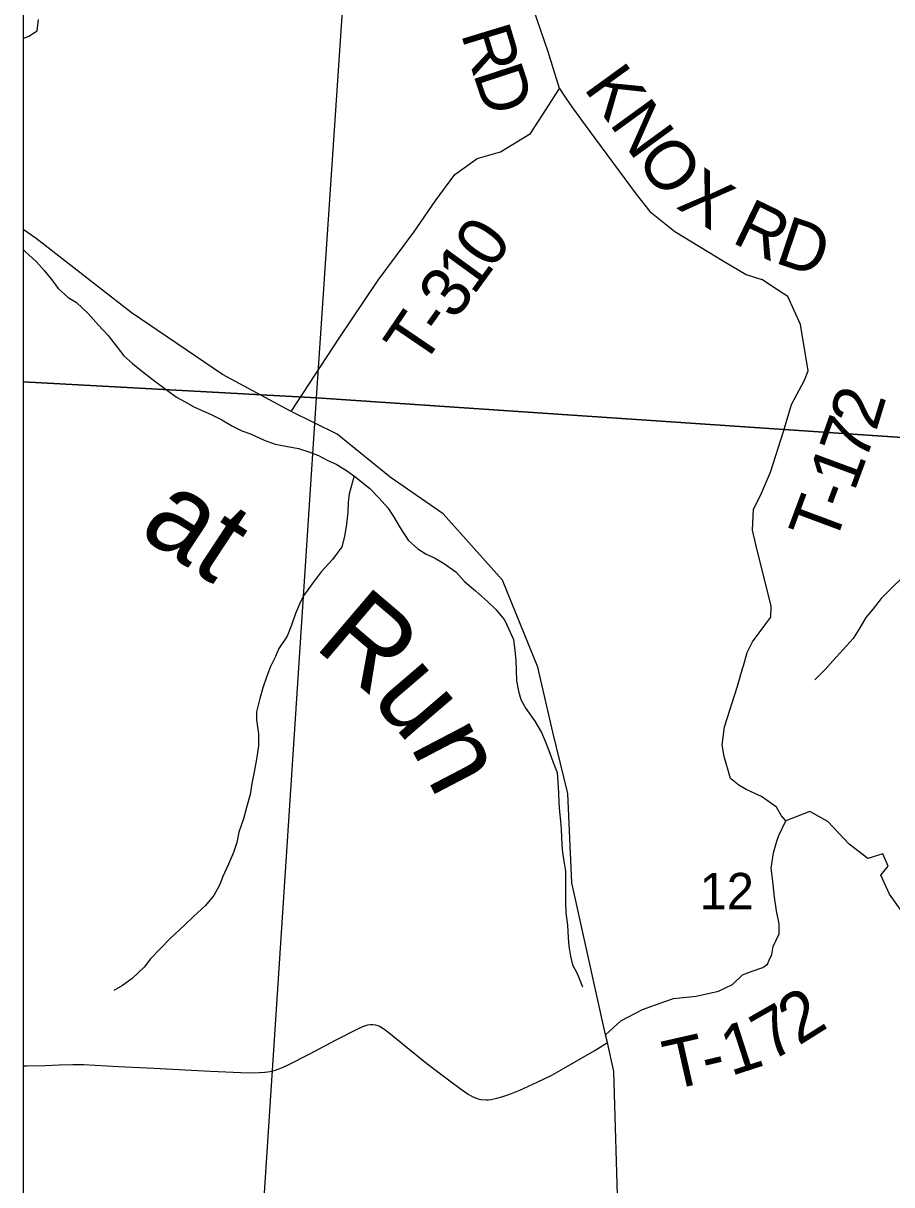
# Model space of a CAD drawing. Extents: x 0 to 34, y 0 to 22.
# Drawn here: x 2.1 to 3.095, y 17.112 to 18.443 of the extents above; entities that cross this region are included whole.
import ezdxf

# ---------------------------------------------------------------- set-up
doc = ezdxf.new("R2010")
doc.units = 0
for name, color, linetype in [('GM_X_Corporation', 7, 'Continuous'), ('GM_X_County_Road', 7, 'Continuous'), ('GM_X_Minor_River', 7, 'Continuous'), ('GM_X_Minor_River_Text', 7, 'Continuous'), ('GM_X_Section_Text', 7, 'Continuous'), ('GM_X_Township_Road', 7, 'Continuous'), ('GM_X_Township_Road_Text', 7, 'Continuous'), ('SH_Data', 7, 'Continuous')]:
    doc.layers.add(name, color=color, linetype=linetype)

msp = doc.modelspace()

# ---------------------------------------------------------------- linework, layer by layer
at = {"layer": 'GM_X_Corporation'}
for points in [[(2.1, 19.0816), (2.1, 14.1), (3.1902, 14.1), (3.1919, 14.1255), (3.2339, 14.7735), (3.2844, 15.554), (3.3059, 15.8844), (3.3516, 16.5898), (3.3951, 17.2616), (3.507, 18.9883), (2.9513, 19.0267), (2.509, 19.0572), (2.4972, 19.0545), (2.4649, 19.0567)], [(2.1, 19.0812), (2.1, 18.0323), (2.436, 18.0137), (2.5061, 19.0541)], [(2.5061, 19.0541), (2.5182, 19.0533), (3.5166, 18.9866), (3.4457, 17.9455), (2.436, 18.0137)], [(2.1, 18.0323), (2.1, 16.9887), (2.3682, 16.9741), (2.436, 18.0137)], [(2.436, 18.0137), (3.4457, 17.9455), (3.3779, 16.9127), (2.3682, 16.9741)]]:
    msp.add_lwpolyline(points, close=True, dxfattribs=at)
at = {"layer": 'GM_X_County_Road'}
for points in [[(2.7818, 17.0745), (2.777, 17.2417), (2.7694, 17.2751), (2.7674, 17.2839), (2.7452, 17.3837), (2.7286, 17.4581), (2.7242, 17.5602), (2.7069, 17.6307), (2.6896, 17.7051), (2.6491, 17.8048), (2.5813, 17.8808), (2.5204, 17.9231), (2.4599, 17.9722), (2.4069, 17.9982), (2.3284, 18.0405), (2.2238, 18.1118), (2.115, 18.1965), (2.1, 18.2067)], [(2.1, 17.2482), (2.104, 17.2481), (2.1257, 17.2486), (2.1412, 17.2493), (2.1567, 17.2499), (2.1662, 17.2498), (2.169, 17.2497), (2.2092, 17.2475), (2.2495, 17.2456), (2.3147, 17.2421), (2.3581, 17.2403), (2.3706, 17.2404), (2.3769, 17.2409), (2.3831, 17.2419), (2.3892, 17.2434), (2.3922, 17.2443), (2.398, 17.2466), (2.4037, 17.2492), (2.4286, 17.2621), (2.4588, 17.2779), (2.4836, 17.2908), (2.4893, 17.2933), (2.495, 17.2951), (2.4979, 17.2955), (2.5008, 17.2956), (2.5037, 17.2952), (2.5065, 17.2944), (2.5092, 17.2932), (2.5144, 17.2899), (2.5193, 17.2862), (2.5361, 17.2724), (2.5627, 17.2508), (2.5873, 17.2321), (2.6022, 17.2211), (2.6098, 17.2157), (2.6153, 17.2126), (2.6182, 17.2114), (2.6213, 17.2104), (2.6244, 17.2098), (2.6304, 17.2093), (2.6333, 17.2094), (2.6364, 17.2098), (2.6426, 17.211), (2.6486, 17.2126), (2.6575, 17.2157), (2.669, 17.2204), (2.6889, 17.2294), (2.7057, 17.2376), (2.7193, 17.2451), (2.7543, 17.2654), (2.7694, 17.2751)]]:
    msp.add_lwpolyline(points, dxfattribs=at)
at = {"layer": 'GM_X_Minor_River'}
for p, q in [((2.1161, 18.4345), (2.1176, 18.4474)), ((2.1, 18.4258), (2.1063, 18.4284)), ((2.1063, 18.4284), (2.1161, 18.4345)), ((2.4793, 17.9243), (2.4734, 17.904)), ((2.4723, 17.8938), (2.4719, 17.8828)), ((2.4734, 17.904), (2.4723, 17.8938)), ((2.4719, 17.8828), (2.4705, 17.8691)), ((2.4705, 17.8691), (2.4682, 17.8551)), ((2.4682, 17.8551), (2.4652, 17.8429)), ((2.4652, 17.8429), (2.4543, 17.8285)), ((2.4543, 17.8285), (2.4415, 17.8144)), ((2.4415, 17.8144), (2.431, 17.8007)), ((2.431, 17.8007), (2.4212, 17.787)), ((2.4212, 17.787), (2.4167, 17.7772)), ((2.4167, 17.7772), (2.4121, 17.7665)), ((2.4121, 17.7665), (2.4073, 17.7532)), ((2.4073, 17.7532), (2.4024, 17.7407)), ((2.4024, 17.7407), (2.393, 17.7266)), ((2.393, 17.7266), (2.3892, 17.7172)), ((2.3892, 17.7172), (2.3832, 17.7061)), ((2.3787, 17.6936), (2.3746, 17.6815)), ((2.3832, 17.7061), (2.3787, 17.6936)), ((2.3746, 17.6815), (2.3712, 17.6693)), ((2.3712, 17.6693), (2.3675, 17.6541)), ((2.3675, 17.6541), (2.3672, 17.6447)), ((2.3672, 17.6447), (2.3695, 17.6288)), ((2.3695, 17.6288), (2.3695, 17.6151)), ((2.3695, 17.6151), (2.3673, 17.5996)), ((2.3651, 17.5871), (2.3621, 17.5719)), ((2.3673, 17.5996), (2.3651, 17.5871)), ((2.3621, 17.5719), (2.3599, 17.5594)), ((2.3599, 17.5594), (2.3558, 17.5442)), ((2.3558, 17.5442), (2.3524, 17.5313)), ((2.3524, 17.5313), (2.3472, 17.5161)), ((2.3472, 17.5161), (2.3446, 17.5043)), ((2.3446, 17.5043), (2.3408, 17.4926)), ((2.3408, 17.4926), (2.3352, 17.4793)), ((2.3352, 17.4793), (2.3288, 17.4652)), ((2.3251, 17.4554), (2.3183, 17.4436)), ((2.3288, 17.4652), (2.3251, 17.4554)), ((2.3183, 17.4436), (2.3085, 17.4318)), ((2.3085, 17.4318), (2.2953, 17.4192)), ((2.2953, 17.4192), (2.2847, 17.4093)), ((2.2847, 17.4093), (2.2685, 17.3941)), ((2.2685, 17.3941), (2.2564, 17.3819)), ((2.2564, 17.3819), (2.2459, 17.3709)), ((2.2387, 17.3614), (2.2248, 17.3484)), ((2.2459, 17.3709), (2.2387, 17.3614)), ((2.2248, 17.3484), (2.2138, 17.3404)), ((2.2138, 17.3404), (2.204, 17.3347))]:
    msp.add_line(p, q, dxfattribs=at)
for points in [[(2.1, 18.1839), (2.1022, 18.1817), (2.1151, 18.1696), (2.1239, 18.1598), (2.1326, 18.1492), (2.1402, 18.139), (2.1516, 18.1288), (2.1611, 18.1232), (2.1744, 18.1107), (2.1862, 18.0971), (2.1972, 18.0854), (2.2075, 18.0718), (2.2154, 18.062), (2.2253, 18.0533), (2.2371, 18.0435), (2.2507, 18.033), (2.2652, 18.0221), (2.2758, 18.0145), (2.2856, 18.0093), (2.2955, 18.0036), (2.3057, 17.9988), (2.3152, 17.9946), (2.3277, 17.9886), (2.3399, 17.9815), (2.3505, 17.9762), (2.3603, 17.9725), (2.3763, 17.9653), (2.3888, 17.9608), (2.4009, 17.9586), (2.4156, 17.9557), (2.4274, 17.9519), (2.4384, 17.9478), (2.449, 17.9422), (2.4585, 17.9377), (2.4706, 17.9305), (2.4816, 17.9226), (2.4972, 17.9098), (2.5078, 17.8988), (2.5177, 17.8879), (2.5242, 17.8777), (2.5318, 17.8648), (2.5413, 17.8509), (2.5523, 17.8407), (2.5618, 17.8347), (2.5713, 17.8305), (2.5815, 17.8245), (2.5959, 17.8143), (2.6058, 17.8034), (2.6183, 17.7925), (2.632, 17.7804), (2.6415, 17.7713), (2.6517, 17.7593), (2.6563, 17.7494), (2.6617, 17.7369), (2.6632, 17.7244), (2.6644, 17.7131), (2.6648, 17.7021)], [(3.2864, 17.8667), (3.2603, 17.8666), (3.246, 17.8646), (3.2335, 17.8634), (3.2236, 17.8619), (3.2138, 17.8611), (3.1987, 17.8606), (3.1847, 17.8568), (3.1718, 17.8529), (3.1571, 17.8438), (3.145, 17.8312), (3.1314, 17.8262), (3.119, 17.8171), (3.1091, 17.8094), (3.0956, 17.7961), (3.0831, 17.7839), (3.0741, 17.7721), (3.0658, 17.7619), (3.0586, 17.7501), (3.0511, 17.7379), (3.0398, 17.7254), (3.0277, 17.7124), (3.0191, 17.7025), (3.007, 17.6907)], [(2.6648, 17.7021), (2.6652, 17.6896), (2.6676, 17.6778), (2.6702, 17.668), (2.6759, 17.6578), (2.6862, 17.6434), (2.6938, 17.6302), (2.698, 17.6204), (2.7022, 17.6098), (2.7068, 17.5969), (2.7118, 17.5844), (2.7126, 17.5735), (2.7134, 17.5606), (2.7138, 17.5496), (2.7146, 17.5393), (2.7158, 17.5287), (2.7166, 17.5193), (2.717, 17.5098), (2.7178, 17.4958), (2.7193, 17.4852), (2.7213, 17.4712), (2.7214, 17.4363), (2.7218, 17.4234), (2.7238, 17.4094), (2.7246, 17.3954), (2.7254, 17.3855), (2.7273, 17.3738), (2.7296, 17.3639), (2.7349, 17.3541), (2.741, 17.3386)]]:
    msp.add_lwpolyline(points, dxfattribs=at)
at = {"layer": 'GM_X_Township_Road'}
for points in [[(2.7147, 18.3683), (2.7016, 18.4104), (2.6765, 18.484), (2.664, 18.531), (2.6644, 18.5728), (2.6605, 18.6092), (2.651, 18.6323), (2.637, 18.6482), (2.6237, 18.6649), (2.6047, 18.7594), (2.5903, 18.8076), (2.5713, 18.8307), (2.4999, 18.87), (2.4984, 18.9072), (2.4956, 18.9812), (2.4916, 18.9912)], [(2.4069, 17.9982), (2.4619, 18.0822), (2.5066, 18.1486), (2.5476, 18.2037), (2.5719, 18.2391), (2.5946, 18.2699), (2.6202, 18.288), (2.6469, 18.2957), (2.6814, 18.317), (2.6989, 18.3439), (2.7147, 18.3683), (2.7204, 18.3597)], [(2.7204, 18.3597), (2.7295, 18.3461), (2.7493, 18.319), (2.8024, 18.2473), (2.818, 18.2274), (2.8466, 18.2044), (2.9033, 18.17), (2.9285, 18.1554), (2.9464, 18.1494)], [(2.9253, 17.7067), (2.9296, 17.722), (2.9357, 17.7341), (2.9512, 17.7547), (2.9569, 17.7626), (2.9573, 17.7752), (2.9397, 17.8457), (2.9356, 17.862), (2.9368, 17.8863), (2.9451, 17.9019), (2.9565, 17.9285), (2.9712, 17.9752), (2.9803, 18.0063), (2.9955, 18.034), (2.9997, 18.045), (2.9906, 18.0978), (2.9762, 18.13), (2.9644, 18.1378), (2.9464, 18.1494)], [(2.9549, 17.3693), (2.9578, 17.3759), (2.9593, 17.3851), (2.9662, 17.3995), (2.9665, 17.4109), (2.9631, 17.4257), (2.9608, 17.4416), (2.9589, 17.4594), (2.957, 17.4746), (2.9597, 17.4925), (2.9638, 17.5057), (2.9661, 17.5122), (2.9738, 17.5291), (2.9691, 17.5346), (2.9631, 17.5448), (2.946, 17.5569), (2.9376, 17.5607), (2.9285, 17.5649), (2.9202, 17.5698), (2.9107, 17.5774), (2.9031, 17.6028), (2.9008, 17.6161), (2.9035, 17.6366), (2.9186, 17.6833), (2.9247, 17.7047), (2.9253, 17.7067)], [(3.2664, 17.2994), (3.185, 17.3582), (3.1212, 17.4051), (3.0929, 17.4449), (3.0828, 17.4667), (3.0914, 17.4772), (3.0852, 17.4913), (3.068, 17.4857), (3.0464, 17.5021), (3.022, 17.5284), (3.0014, 17.5399), (2.9738, 17.5291)], [(2.7674, 17.2839), (2.7848, 17.2998), (2.8095, 17.3127), (2.8352, 17.3218), (2.8451, 17.3253), (2.8713, 17.328), (2.8967, 17.3337), (2.9127, 17.3413), (2.9241, 17.3524), (2.9354, 17.3569), (2.9476, 17.3611), (2.9529, 17.3646), (2.9549, 17.3693)]]:
    msp.add_lwpolyline(points, dxfattribs=at)
at = {"layer": 'SH_Data'}
msp.add_line((2.1, 20.9), (2.1, 14.1), dxfattribs=at)

# ---------------------------------------------------------------- texts
at = {"layer": 'GM_X_Minor_River_Text'}
for s, rotation, p in [('at', 326.6036, (2.2303, 17.8578)), ('R', 319.6024, (2.4317, 17.7287)), ('u', 310.6023, (2.497, 17.6689)), ('n', 297.6024, (2.5428, 17.6149))]:
    msp.add_text(s, height=0.0947, rotation=rotation, dxfattribs=at).set_placement(p)
at = {"layer": 'GM_X_Section_Text'}
msp.add_text('12', height=0.04186, rotation=0, dxfattribs=at).set_placement((2.8751, 17.4275))
at = {"layer": 'GM_X_Township_Road_Text'}
for s, rotation, p in [('R', 286.9189, (2.6013, 18.4314)), ('D', 288.1467, (2.6153, 18.3855)), ('K', 305.9395, (2.7414, 18.3688)), ('N', 306.0321, (2.7708, 18.3282)), ('O', 307.058, (2.8008, 18.2869)), ('X', 327.2475, (2.8469, 18.2322)), ('R', 334.154, (2.9105, 18.1926)), ('0', 55.0391, (2.6372, 18.1594)), ('D', 341.4359, (2.9598, 18.1692)), ('1', 53.9687, (2.6159, 18.1302)), ('3', 53.0031, (2.5943, 18.1014)), ('T', 55.8369, (2.5573, 18.0478)), ('-', 54.5041, (2.5809, 18.0827)), ('2', 72.9983, (3.0773, 17.9746)), ('7', 70.4882, (3.0648, 17.939)), ('1', 69.7039, (3.0523, 17.9054)), ('-', 69.5553, (3.0441, 17.8834)), ('T', 69.5453, (3.0293, 17.8436)), ('2', 32.0057, (2.9884, 17.2708)), ('7', 29.6979, (2.9558, 17.2522)), ('1', 17.9414, (2.9109, 17.2363)), ('T', 12.7659, (2.8414, 17.2201)), ('-', 13.2923, (2.8834, 17.2296))]:
    msp.add_text(s, height=0.0568, rotation=rotation, dxfattribs=at).set_placement(p)

doc.saveas('drawing.dxf')
